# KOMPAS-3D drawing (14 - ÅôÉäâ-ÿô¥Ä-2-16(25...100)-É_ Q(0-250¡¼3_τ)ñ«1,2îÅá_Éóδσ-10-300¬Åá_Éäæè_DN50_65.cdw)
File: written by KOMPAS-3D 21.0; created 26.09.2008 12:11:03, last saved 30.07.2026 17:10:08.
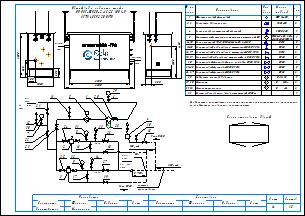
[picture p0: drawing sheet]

Sheets 1-2: A3, landscape

Document properties: Наименование: Макро:21; Автор: RaskoAdmin; Форматы листов документа: 2xA3; Полное имя файла: \\ur38nt01\Departments\КТО\КБ ПУРДГ\Заявки\Прайс-лист на типовые шкафы ГРПШ\ПУРДГ_стандарт_30_04_2026\ПУРДГ с РДСК\ПУРДГ-ШУЭО-2-16(25...100)-Р_ Q(0-250нм3_ч)до1,2МПа_Рвых-10-300кПа_РДСК_DN50_65.cdw

Title block, sheet 1: Наименование: Пункт учета газа / ПУГ-Ш-400-Р / ЛГТИ.485922.001ТУ; designation: ЛГТИ.03.4411141; sheet number: 1; Количество листов документа: 2; organisation: ООО "ЭЛЬСТЕР Газэлектроника"; Форматы листов документа: A3; stored path: C:\Рабочие документы\Компас\ПУГ\Схема.cdw; Разработал: Устинов; Проверил: Кошкин; Утвердил: Кошкин
Title block, sheet 2: sheet number: 2; stored path: D:\Рабочие документы\Заявки\ПУРДГ\ПУРДГ-ШУЭО-2-100-Р 4411220.cdw; designation, second copy: ЛГТИ.03.4411141-

Views: Вид 1, Вид 2
Referenced files: wcvoit.frw
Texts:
  Normal
  № на
  схеме
  Усл.
  обозн.
  Марка
  (модель)
  Кол.
  Фильтр газовый фланцевый
  ФГ 16-50
  Регулятор давления газа
  РДСК-50
  Клапан предохранительный сбросной
  КПС DN20
  Измерительный комплекс с ротационным счетчиком Ду50
  СГ-ЭК-Р-(0,2...2,0)-
  Кран кнопочный VE-РАСКО-НЗ-1,6-G1/2-М20
  DN15
  Кран шаровой "под приварку" штуцерный DN20 PN16
  DN20
  Кран шаровой "под приварку" штуцерный DN15 PN16
  Кран шаровой "под приварку" штуцерный п/п DN20 PN16
  Кран шаровой фланцевый с мех. приводом DN50 PN16
  Кран шаровой фланцевый DN50 PN16
  Кран шаровой фланцевый DN65 PN16
  DN50
  DN65
  Индикатор перепада давления
  Манометр
  Манометр-напоромер
  Электрообогреватель взрывозащищенный 400Вт
  Delta 15
  0...     МПа
  0...     кПа
  Общий вид и габариты шкафа
  ПУРДГ-ШУЭО-2-16(25...100)-Р
  Выход газа
  Вход газа
  logo-rasko-ge.png
  DN 1
  местное
  сопротивление
  Римп DN20
  Выход
  газа
  Р=     кПа
  Вход
  Р=       МПа
  PDI
  Схема открывания дверей
  Предприятие изготовитель может заменять комплектующие на аналогичные,
  не ухудшающие заявленных характеристик.
  Должность
  Конструктор
  Фамилия
  Подпись
  Дата
  Согласовано
  Максимкин
  Лист
  Листов
  POLYLINE_STYLE_0.18_RGB_0_0_0
  POLYLINE_STYLE_0.50_RGB_0_0_0
  POLYLINE_STYLE_0.34_RGB_0_0_0
  PHANTOM_RGB_0_0_0_SC_1_THICK_0.18
  K5LT_THIN_RGB_0_0_0_THICK_0.18
  K5LT32769_RGB_0_0_0_THICK_0.18
  K5LT12_RGB_0_0_0_SC_1_THICK_0.18
  K5LT_DASHED_RGB_0_0_0_SC_1_THICK_0.18
  ACISOTGL_RGB_0_0_0_SC_0.8_THICK_0.25
  CONTINUOUS_RGB_0_127_31_THICK_0.3
  CONTINUOUS_RGB_0_0_255_THICK_0.35
  CONTINUOUS_RGB_255_0_0_THICK_0.35
  POLYLINE_STYLE_0.25_RGB_0_0_0
  CONTINUOUS_RGB_0_0_0_THICK_0.5
  POLYLINE_STYLE_0.35_RGB_0_0_255
  CONTINUOUS_RGB_0_0_0_THICK_0.4
  CONTINUOUS_RGB_0_0_0_THICK_0.35
  НЕВИДИМАЯ_RGB_0_0_0_SC_0.3_THICK_0.25
  СONTINUOUS_RGB_0_0_0_THICK_0.25
  ОСЕВАЯ2_RGB_248_153_30_SC_0.3_THICK_0.25
  Без оформления
Dimensions and other numbers on the sheet: 1; 2, 3; 2; 4; 5; 6-10; 11-15; 16, 17; 18, 19; 20; 21-25; 26, 27; 28; 29, 30; 31, 32; 33; 1500; 250; 300; 1050; 550; 305; 2300; 4130; 2000; 2600; 5,,,7DN 1; 7; 30; 12; 21; 22; 23; 11; 6; 29; 24; 31; 8; 16; 13; 26; 18; 10; 15; 25; 32; 9; 3; 17; 14; 27; 19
